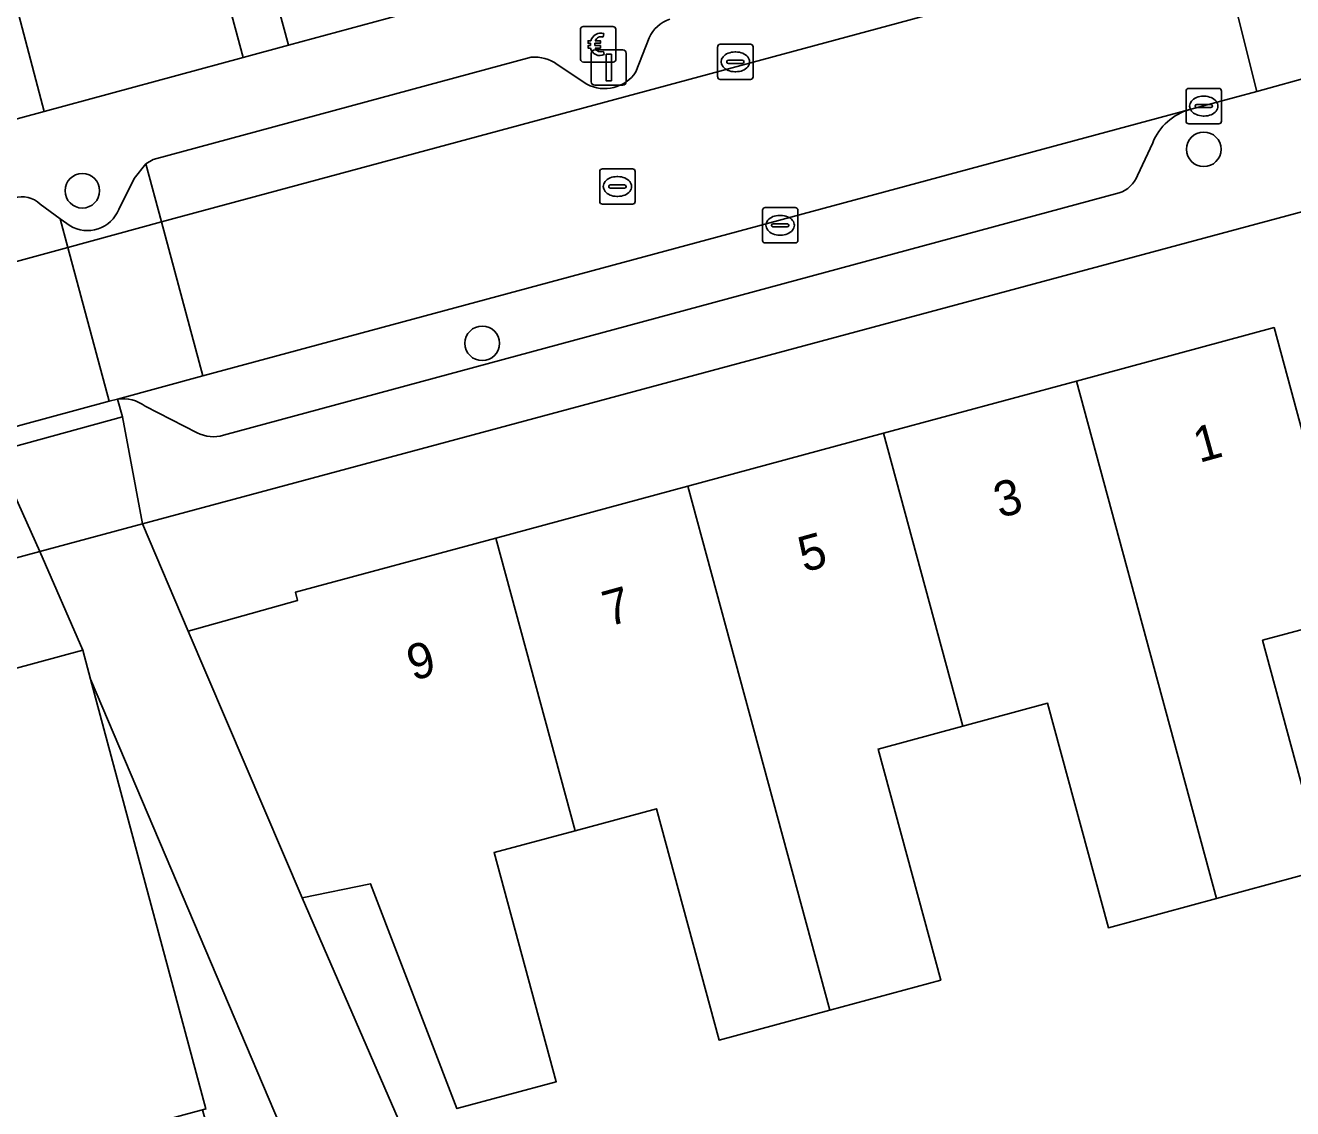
# Model space of a CAD drawing. Extents: x 159262 to 160143, y 383399 to 384319.
# Drawn here: x 159776.11 to 159811.9, y 383788.99 to 383819.59 of the extents above; entities that cross this region are included whole.
import ezdxf

# ---------------------------------------------------------------- set-up
doc = ezdxf.new("R2010")
doc.units = 0
for name, color, linetype in [('IMGEO_Betaalautomaat', 7, 'Continuous'), ('IMGEO_Boom', 7, 'Continuous'), ('IMGEO_Erf', 7, 'Continuous'), ('IMGEO_Groenvoorziening', 7, 'Continuous'), ('IMGEO_Kolk', 7, 'Continuous'), ('IMGEO_Lichtmast', 7, 'Continuous'), ('IMGEO_Pand', 7, 'Continuous'), ('IMGEO_Pand_nummerreeks', 7, 'Continuous'), ('IMGEO_Parkeervlak_open', 7, 'Continuous'), ('IMGEO_Rijbaan_lokaal_open', 7, 'Continuous'), ('IMGEO_Rioolput', 7, 'Continuous'), ('IMGEO_Voetpad_open', 7, 'Continuous')]:
    doc.layers.add(name, color=color, linetype=linetype)

msp = doc.modelspace()

# ---------------------------------------------------------------- linework, layer by layer
at = {"layer": 'IMGEO_Betaalautomaat'}
for p, q in [((159791.785, 383818.631), (159791.785, 383819.472)), ((159791.785, 383819.472), (159791.785, 383818.631)), ((159791.86, 383819.555), (159792.701, 383819.555)), ((159792.701, 383819.555), (159791.86, 383819.555)), ((159792.447, 383819.36), (159792.43, 383819.26)), ((159792.784, 383819.481), (159792.784, 383818.64)), ((159792.784, 383818.64), (159792.784, 383819.481)), ((159792.068, 383819.019), (159792.068, 383819.087)), ((159792.189, 383819.087), (159792.189, 383819.019)), ((159792.71, 383818.556), (159791.869, 383818.556)), ((159791.869, 383818.556), (159792.71, 383818.556)), ((159792.434, 383818.854), (159792.456, 383818.767))]:
    msp.add_line(p, q, dxfattribs=at)
for points in [[(159792.068, 383819.087), (159791.999, 383819.087), (159791.999, 383819.156), (159792.078, 383819.156)], [(159792.073, 383818.95), (159791.999, 383818.95), (159791.999, 383819.019), (159792.068, 383819.019)], [(159792.2, 383819.156), (159792.347, 383819.156), (159792.347, 383819.087), (159792.189, 383819.087)], [(159792.189, 383819.019), (159792.347, 383819.019), (159792.347, 383818.95), (159792.203, 383818.95)]]:
    msp.add_lwpolyline(points, dxfattribs=at)
for centre, radius, start, end in [((159791.863, 383819.478), 0.0779, 92.4484, 184.2845), ((159791.863, 383819.478), 0.0779, 92.4484, 184.2845), ((159792.361, 383819.08), 0.293, 73.014, 165.0139), ((159792.367, 383819.093), 0.179, 69.3236, 159.5683), ((159792.707, 383819.478), 0.0779, 2.4484, 94.2845), ((159792.707, 383819.478), 0.0779, 2.4484, 94.2845), ((159792.334, 383819.005), 0.267, 191.8096, 297.0389), ((159792.367, 383819.02), 0.179, 202.7625, 291.8693), ((159791.863, 383818.634), 0.0779, 182.4484, 274.2845), ((159791.863, 383818.634), 0.0779, 182.4484, 274.2845), ((159792.707, 383818.634), 0.0779, 272.4484, 4.2845), ((159792.707, 383818.634), 0.0779, 272.4484, 4.2845)]:
    msp.add_arc(centre, radius, start, end, dxfattribs=at)
at = {"layer": 'IMGEO_Boom'}
for centre in [(159809.388, 383816.09), (159777.717, 383814.921), (159789.012, 383810.61)]:
    msp.add_circle(centre, 0.489, dxfattribs=at)
at = {"layer": 'IMGEO_Erf'}
for points in [[(159781.244, 383827.509), (159783.539, 383819.032), (159798.168, 383822.992)], [(159813.446, 383814.675), (159779.417, 383805.511), (159780.709, 383802.483), (159783.793, 383803.342), (159783.733, 383803.578), (159789.398, 383805.11), (159794.821, 383806.577), (159800.344, 383808.071), (159805.792, 383809.544), (159811.376, 383811.055), (159813.578, 383802.907), (159811.051, 383802.224), (159812.804, 383795.754), (159809.751, 383794.928), (159806.698, 383794.101), (159804.98, 383800.445), (159802.586, 383799.796), (159800.192, 383799.148), (159801.96, 383792.625), (159798.83, 383791.777), (159795.7, 383790.929), (159793.929, 383797.465), (159791.638, 383796.844), (159789.346, 383796.224), (159791.1, 383789.753), (159788.297, 383788.993), (159785.858, 383795.344), (159783.924, 383794.951), (159788.976, 383783.333)], [(159759.022, 383796.872), (159777.726, 383801.942), (159776.518, 383804.726), (159735.007, 383793.487)]]:
    msp.add_lwpolyline(points, dxfattribs=at)
at = {"layer": 'IMGEO_Groenvoorziening'}
msp.add_lwpolyline([(159777.945, 383801.127), (159781.205, 383788.985), (159781.108, 383788.959), (159781.597, 383787.177), (159783.633, 383787.743)], close=True, dxfattribs=at)
at = {"layer": 'IMGEO_Kolk'}
for p, q in [((159795.66, 383818.135), (159795.66, 383818.987)), ((159795.735, 383819.061), (159796.587, 383819.061)), ((159796.661, 383818.987), (159796.661, 383818.135)), ((159795.919, 383818.555), (159795.919, 383818.567)), ((159795.962, 383818.604), (159796.36, 383818.604)), ((159796.148, 383818.841), (159796.173, 383818.841)), ((159796.403, 383818.567), (159796.403, 383818.555)), ((159796.357, 383818.518), (159795.959, 383818.518)), ((159796.171, 383818.281), (159796.146, 383818.281)), ((159796.587, 383818.061), (159795.735, 383818.061)), ((159808.964, 383817.81), (159809.816, 383817.81)), ((159808.889, 383816.884), (159808.889, 383817.736)), ((159809.377, 383817.59), (159809.402, 383817.59)), ((159809.89, 383817.736), (159809.89, 383816.884)), ((159809.148, 383817.304), (159809.148, 383817.316)), ((159809.586, 383817.267), (159809.188, 383817.267)), ((159809.191, 383817.353), (159809.589, 383817.353)), ((159809.632, 383817.316), (159809.632, 383817.304)), ((159809.816, 383816.81), (159808.964, 383816.81)), ((159809.4, 383817.03), (159809.375, 383817.03)), ((159796.925, 383813.519), (159796.925, 383814.371)), ((159797, 383814.445), (159797.852, 383814.445)), ((159797.926, 383814.371), (159797.926, 383813.519)), ((159797.184, 383813.939), (159797.184, 383813.951)), ((159797.622, 383813.902), (159797.224, 383813.902)), ((159797.227, 383813.988), (159797.625, 383813.988)), ((159797.413, 383814.225), (159797.438, 383814.225)), ((159797.668, 383813.951), (159797.668, 383813.939)), ((159797.436, 383813.665), (159797.411, 383813.665)), ((159797.852, 383813.445), (159797, 383813.445))]:
    msp.add_line(p, q, dxfattribs=at)
for points in [[(159795.66, 383818.135), (159795.66, 383818.987)], [(159795.735, 383819.061), (159796.587, 383819.061)], [(159796.661, 383818.987), (159796.661, 383818.135)], [(159796.587, 383818.061), (159795.735, 383818.061)], [(159808.964, 383817.81), (159809.816, 383817.81)], [(159808.889, 383816.884), (159808.889, 383817.736)], [(159809.89, 383817.736), (159809.89, 383816.884)], [(159809.816, 383816.81), (159808.964, 383816.81)], [(159796.925, 383813.519), (159796.925, 383814.371)], [(159797, 383814.445), (159797.852, 383814.445)], [(159797.926, 383814.371), (159797.926, 383813.519)], [(159797.852, 383813.445), (159797, 383813.445)]]:
    msp.add_lwpolyline(points, dxfattribs=at)
for centre, radius, start, end in [((159795.737, 383818.985), 0.0765, 91.552, 178.448), ((159795.737, 383818.985), 0.0765, 91.552, 178.448), ((159796.585, 383818.985), 0.0765, 1.552, 88.448), ((159796.585, 383818.985), 0.0765, 1.552, 88.448), ((159795.959, 383818.564), 0.0403, 85.8775, 175.7526), ((159795.956, 383818.554), 0.0366, 178.938, 274.7102), ((159796.36, 383818.561), 0.043, 264.8664, 352.4533), ((159796.364, 383818.566), 0.0386, 1.7309, 96.639), ((159795.737, 383818.137), 0.0765, 181.552, 268.448), ((159795.737, 383818.137), 0.0765, 181.552, 268.448), ((159796.585, 383818.137), 0.0765, 271.552, 358.448), ((159796.585, 383818.137), 0.0765, 271.552, 358.448), ((159808.966, 383817.734), 0.0765, 91.552, 178.448), ((159808.966, 383817.734), 0.0765, 91.552, 178.448), ((159809.814, 383817.734), 0.0765, 1.552, 88.448), ((159809.814, 383817.734), 0.0765, 1.552, 88.448), ((159809.188, 383817.313), 0.0403, 85.8775, 175.7526), ((159809.185, 383817.303), 0.0366, 178.938, 274.7102), ((159809.589, 383817.31), 0.043, 264.8664, 352.4533), ((159809.593, 383817.315), 0.0386, 1.7309, 96.639), ((159808.966, 383816.886), 0.0765, 181.552, 268.448), ((159808.966, 383816.886), 0.0765, 181.552, 268.448), ((159809.814, 383816.886), 0.0765, 271.552, 358.448), ((159809.814, 383816.886), 0.0765, 271.552, 358.448), ((159797.002, 383814.369), 0.0765, 91.552, 178.448), ((159797.002, 383814.369), 0.0765, 91.552, 178.448), ((159797.85, 383814.369), 0.0765, 1.552, 88.448), ((159797.85, 383814.369), 0.0765, 1.552, 88.448), ((159797.224, 383813.948), 0.0403, 85.8775, 175.7526), ((159797.221, 383813.938), 0.0366, 178.938, 274.7102), ((159797.625, 383813.945), 0.043, 264.8664, 352.4533), ((159797.629, 383813.95), 0.0386, 1.7309, 96.639), ((159797.002, 383813.521), 0.0765, 181.552, 268.448), ((159797.002, 383813.521), 0.0765, 181.552, 268.448), ((159797.85, 383813.521), 0.0765, 271.552, 358.448), ((159797.85, 383813.521), 0.0765, 271.552, 358.448)]:
    msp.add_arc(centre, radius, start, end, dxfattribs=at)
for centre, major_axis, ratio, start_param, end_param in [((159796.147, 383818.561), (-0.387, 0.002), 0.722429, 4.712389, 7.853982), ((159796.172, 383818.561), (-0.39, 0.002), 0.717154, 1.570796, 4.712389), ((159809.376, 383817.31), (-0.387, 0.002), 0.722429, 4.712389, 7.853982), ((159809.401, 383817.31), (-0.39, 0.002), 0.717154, 1.570796, 4.712389), ((159797.412, 383813.945), (-0.387, 0.002), 0.722429, 4.712389, 7.853982), ((159797.437, 383813.945), (-0.39, 0.002), 0.717154, 1.570796, 4.712389)]:
    msp.add_ellipse(centre, major_axis=major_axis, ratio=ratio, start_param=start_param, end_param=end_param, dxfattribs=at)
at = {"layer": 'IMGEO_Lichtmast'}
for p, q in [((159792.189, 383818.9), (159792.979, 383818.9)), ((159792.979, 383818.9), (159792.189, 383818.9)), ((159792.089, 383818), (159792.089, 383818.8)), ((159792.089, 383818.8), (159792.089, 383818)), ((159793.079, 383818.8), (159793.079, 383818)), ((159793.079, 383818), (159793.079, 383818.8)), ((159792.979, 383817.9), (159792.189, 383817.9)), ((159792.189, 383817.9), (159792.979, 383817.9))]:
    msp.add_line(p, q, dxfattribs=at)
msp.add_lwpolyline([(159792.509, 383818.775), (159792.659, 383818.775), (159792.659, 383818.025), (159792.509, 383818.025), (159792.509, 383818.775)], dxfattribs=at)
for centre, start, end in [((159792.189, 383818.8), 90, 180), ((159792.189, 383818.8), 90, 180), ((159792.979, 383818.8), 0, 90), ((159792.979, 383818.8), 360, 90), ((159792.189, 383818), 180, 270), ((159792.189, 383818), 180, 270), ((159792.979, 383818), 270, 0), ((159792.979, 383818), 270, 0)]:
    msp.add_arc(centre, 0.1, start, end, dxfattribs=at)
at = {"layer": 'IMGEO_Pand'}
for points in [[(159780.061, 383826.825), (159777.749, 383826.021), (159776.017, 383832.553), (159775.641, 383832.453), (159772.809, 383831.702), (159776.639, 383817.16), (159782.255, 383818.684)], [(159771.151, 383815.672), (159776.639, 383817.16), (159772.809, 383831.702), (159769.601, 383830.851), (159771.32, 383824.37), (159769.021, 383823.759)], [(159805.792, 383809.544), (159809.751, 383794.928), (159812.804, 383795.754), (159811.051, 383802.224), (159813.578, 383802.907), (159811.376, 383811.055)], [(159805.792, 383809.544), (159800.344, 383808.071), (159802.586, 383799.796), (159804.98, 383800.445), (159806.698, 383794.101), (159809.751, 383794.928)], [(159800.344, 383808.071), (159794.821, 383806.577), (159798.83, 383791.777), (159801.96, 383792.625), (159800.192, 383799.148), (159802.586, 383799.796)], [(159794.821, 383806.577), (159789.398, 383805.11), (159791.638, 383796.844), (159793.929, 383797.465), (159795.7, 383790.929), (159798.83, 383791.777)], [(159791.638, 383796.844), (159789.398, 383805.11), (159783.733, 383803.578), (159783.793, 383803.342), (159780.709, 383802.483), (159783.924, 383794.951), (159785.858, 383795.344), (159788.297, 383788.993), (159791.1, 383789.753), (159789.346, 383796.224)], [(159777.945, 383801.127), (159777.726, 383801.942), (159759.022, 383796.872), (159758.307, 383796.678), (159761.098, 383786.327), (159761.798, 383783.735), (159761.935, 383783.772), (159780.936, 383788.912), (159781.108, 383788.959), (159781.205, 383788.985)]]:
    msp.add_lwpolyline(points, close=True, dxfattribs=at)
at = {"layer": 'IMGEO_Parkeervlak_open'}
for points in [[(159779.954, 383814.038), (159807.933, 383821.6)], [(159793.726, 383819.241), (159793.35, 383818.276)], [(159790.394, 383818.691), (159779.716, 383815.804)], [(159791.967, 383817.93), (159791.129, 383818.484)], [(159808.996, 383817.216), (159781.118, 383809.691)], [(159807.517, 383815.352), (159807.947, 383816.275)], [(159777.369, 383813.93), (159777.093, 383814.13), (159777.31, 383813.318), (159779.954, 383814.038), (159779.514, 383815.681), (159779.177, 383815.27), (159778.744, 383814.392)], [(159779.716, 383815.804), (159779.514, 383815.681)], [(159779.514, 383815.681), (159779.954, 383814.038)], [(159781.7, 383808.014), (159806.997, 383814.86)], [(159777.093, 383814.13), (159776.522, 383814.544)], [(159777.31, 383813.318), (159777.093, 383814.13)], [(159762.932, 383809.399), (159777.31, 383813.318)], [(159781.118, 383809.691), (159778.709, 383809.036)], [(159779.493, 383808.832), (159780.962, 383808.083)]]:
    msp.add_lwpolyline(points, dxfattribs=at)
for centre, radius, start, end in [((159794.618, 383818.834), 0.981, 108.578, 155.5055), ((159790.49, 383817.623), 1.072, 53.417, 95.125), ((159792.467, 383818.869), 1.064, 241.9671, 326.1249), ((159809.425, 383815.682), 1.593, 105.6413, 158.1458), ((159806.749, 383815.643), 0.822, 287.5866, 339.2437), ((159776.018, 383814.035), 0.716, 45.2925, 108.0505), ((159777.858, 383814.751), 0.955, 239.1884, 337.9563), ((159778.868, 383808.037), 1.011, 51.8079, 99.0218), ((159781.418, 383808.978), 1.005, 243.0144, 286.3028)]:
    msp.add_arc(centre, radius, start, end, dxfattribs=at)
at = {"layer": 'IMGEO_Rijbaan_lokaal_open'}
for points in [[(159818.156, 383828.416), (159813.846, 383827.217), (159814.865, 383823.438), (159811.373, 383822.538), (159809.783, 383822.128), (159810.888, 383817.723), (159812.514, 383818.172), (159816.064, 383819.153), (159817.391, 383814.24), (159820.841, 383815.179), (159820.687, 383815.791), (159821.45, 383816.037), (159821.238, 383816.833)], [(159807.933, 383821.6), (159779.954, 383814.038), (159781.118, 383809.691), (159808.996, 383817.216), (159810.888, 383817.723), (159809.783, 383822.128)], [(159778.709, 383809.036), (159781.118, 383809.691), (159779.954, 383814.038), (159777.31, 383813.318), (159778.473, 383808.972)], [(159769.839, 383806.637), (159770.158, 383806.723), (159775.1, 383808.06), (159778.473, 383808.972), (159777.31, 383813.318), (159762.932, 383809.399), (159757.045, 383807.806), (159737.05, 383802.372), (159736.568, 383802.249), (159737.771, 383797.988), (159748.262, 383800.807), (159753.374, 383802.176), (159754.435, 383802.471), (159763.42, 383804.901)]]:
    msp.add_lwpolyline(points, close=True, dxfattribs=at)
msp.add_lwpolyline([(159788.296, 383781.119), (159788.976, 383783.333), (159783.924, 383794.951), (159780.709, 383802.483), (159779.417, 383805.511), (159776.518, 383804.726), (159777.726, 383801.942), (159777.945, 383801.127), (159783.633, 383787.743), (159783.792, 383787.368)], dxfattribs=at)
at = {"layer": 'IMGEO_Rioolput'}
for p, q in [((159792.329, 383814.614), (159792.329, 383815.466)), ((159792.404, 383815.54), (159793.256, 383815.54)), ((159792.817, 383815.32), (159792.842, 383815.32)), ((159793.33, 383815.466), (159793.33, 383814.614)), ((159792.588, 383815.034), (159792.588, 383815.046)), ((159793.026, 383814.997), (159792.628, 383814.997)), ((159792.631, 383815.083), (159793.029, 383815.083)), ((159793.072, 383815.046), (159793.072, 383815.034)), ((159792.84, 383814.76), (159792.815, 383814.76)), ((159793.256, 383814.54), (159792.404, 383814.54))]:
    msp.add_line(p, q, dxfattribs=at)
for points in [[(159792.329, 383814.614), (159792.329, 383815.466)], [(159792.404, 383815.54), (159793.256, 383815.54)], [(159793.33, 383815.466), (159793.33, 383814.614)], [(159793.256, 383814.54), (159792.404, 383814.54)]]:
    msp.add_lwpolyline(points, dxfattribs=at)
for centre, radius, start, end in [((159792.406, 383815.464), 0.0765, 91.552, 178.448), ((159792.406, 383815.464), 0.0765, 91.552, 178.448), ((159793.254, 383815.464), 0.0765, 1.552, 88.448), ((159793.254, 383815.464), 0.0765, 1.552, 88.448), ((159792.628, 383815.043), 0.0403, 85.8775, 175.7526), ((159792.625, 383815.033), 0.0366, 178.938, 274.7102), ((159793.029, 383815.04), 0.043, 264.8664, 352.4533), ((159793.033, 383815.045), 0.0386, 1.7309, 96.639), ((159792.406, 383814.616), 0.0765, 181.552, 268.448), ((159792.406, 383814.616), 0.0765, 181.552, 268.448), ((159793.254, 383814.616), 0.0765, 271.552, 358.448), ((159793.254, 383814.616), 0.0765, 271.552, 358.448)]:
    msp.add_arc(centre, radius, start, end, dxfattribs=at)
for centre, major_axis, ratio, start_param, end_param in [((159792.816, 383815.04), (-0.387, 0.002), 0.722429, 4.712389, 7.853982), ((159792.841, 383815.04), (-0.39, 0.002), 0.717154, 1.570796, 4.712389)]:
    msp.add_ellipse(centre, major_axis=major_axis, ratio=ratio, start_param=start_param, end_param=end_param, dxfattribs=at)
at = {"layer": 'IMGEO_Voetpad_open'}
for points in [[(159773.045, 383852.196), (159780.061, 383826.825), (159782.255, 383818.684), (159783.539, 383819.032), (159781.244, 383827.509), (159780.656, 383829.644), (159779.807, 383832.844), (159778.325, 383838.427), (159776.858, 383843.958), (159775.439, 383848.705)], [(159807.933, 383821.6), (159809.783, 383822.128), (159811.373, 383822.538), (159810.41, 383826.285), (159798.168, 383822.992), (159783.539, 383819.032), (159782.255, 383818.684), (159776.639, 383817.16), (159771.151, 383815.672), (159765.66, 383814.182), (159760.083, 383812.67), (159756.052, 383811.573), (159731.977, 383805.001), (159732.956, 383801.323)], [(159793.35, 383818.276), (159793.726, 383819.241)], [(159778.744, 383814.392), (159779.177, 383815.27), (159779.514, 383815.681), (159779.716, 383815.804), (159790.394, 383818.691)], [(159778.709, 383809.036), (159778.853, 383808.533), (159779.417, 383805.511), (159813.446, 383814.675), (159812.514, 383818.172)], [(159791.129, 383818.484), (159791.967, 383817.93)], [(159812.514, 383818.172), (159810.888, 383817.723), (159808.996, 383817.216)], [(159807.947, 383816.275), (159807.517, 383815.352)], [(159806.997, 383814.86), (159781.7, 383808.014)], [(159776.522, 383814.544), (159777.093, 383814.13), (159777.369, 383813.93)], [(159780.962, 383808.083), (159779.493, 383808.832)], [(159776.518, 383804.726), (159775.248, 383807.545), (159775.1, 383808.06), (159770.158, 383806.723), (159769.839, 383806.637)], [(159734.243, 383796.397), (159735.007, 383793.487), (159776.518, 383804.726)]]:
    msp.add_lwpolyline(points, dxfattribs=at)
for points in [[(159778.473, 383808.972), (159775.1, 383808.06), (159775.248, 383807.545), (159778.853, 383808.533), (159778.709, 383809.036)], [(159778.853, 383808.533), (159775.248, 383807.545), (159776.518, 383804.726), (159779.417, 383805.511)]]:
    msp.add_lwpolyline(points, close=True, dxfattribs=at)
for centre, radius, start, end in [((159794.618, 383818.834), 0.981, 108.578, 155.5055), ((159790.49, 383817.623), 1.072, 53.417, 95.125), ((159792.467, 383818.869), 1.064, 241.9671, 326.1249), ((159809.425, 383815.682), 1.593, 105.6413, 158.1458), ((159806.749, 383815.643), 0.822, 287.5866, 339.2437), ((159776.018, 383814.035), 0.716, 45.2925, 108.0505), ((159777.858, 383814.751), 0.955, 239.1884, 337.9563), ((159778.868, 383808.037), 1.011, 51.8079, 99.0218), ((159781.418, 383808.978), 1.005, 243.0144, 286.3028)]:
    msp.add_arc(centre, radius, start, end, dxfattribs=at)

# ---------------------------------------------------------------- texts
at = {"layer": 'IMGEO_Pand_nummerreeks'}
for s, p in [('1', (159809.261, 383807.229)), ('3', (159803.626, 383805.667)), ('5', (159798.101, 383804.135)), ('7', (159792.576, 383802.604)), ('9', (159787.051, 383801.072))]:
    msp.add_text(s, height=1, rotation=15.4928, dxfattribs=at).set_placement(p)

doc.saveas('drawing.dxf')
